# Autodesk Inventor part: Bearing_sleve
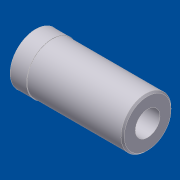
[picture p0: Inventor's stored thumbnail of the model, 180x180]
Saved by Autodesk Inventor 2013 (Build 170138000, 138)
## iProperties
Shininess: 50.0
Length Units: 11269
Angle Units: 11279
Time Units: 11290
Mass Units: 11283
Length Display Precision: 3
Angle Display Precision: 2
Created: 2001-04
Part Number: Bearing_sleve
Material: Standard
Document SubType Name: Modellieren
Designer: dl
Density: 1 g/cm^3
Density: 0.0
Volumn: 0.0
Area: 0.0
PropertySet Name: Model Information
Control State: 0
Master: False
Checked Out: False
Author: dl
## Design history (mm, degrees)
body "Solid1"
sketch "Sketch2"
  geometry: C1 r 10 at (0, 0) reference; 1 further point
  constraints: 1 coincident
revolve "Revolution1" stored, may be unused: angle "d6" = 90 deg
hole "Hole1" sketch "Sketch2" diameter "d7" = 15; stored, may be unused: countersink angle "d11" = 60 deg, drill point angle "d13" = 118 deg; dims "d8" = 6, "d9" = 4, "d10" = 2, "d12" = 8
chamfer "Chamfer1" distance "d14" = 1; stored, may be unused: second distance "d15" = 1, angle "d16" = 45 deg
sketch "Sketch1"
  geometry: L1 (0, 0)-(0, 10); L2 (0, 10)-(2, 10); L3 (2, 10)-(2, 15.5); L4 (2, 15.5)-(12, 15.5); L5 (12, 15.5)-(12, 15.2); L6 (12, 15.2)-(70, 15.2); L7 (70, 15.2)-(70, 0); L8 (70, 0)-(0, 0)
  constraints: 16 end point, 6 parallel, 1 perpendicular, 1 vertical
  dimensions: "d0" = 2 distance of L1.end L2.end; "d1" = 10 distance of L1.start L1.end; "d2" = 15.5 distance between parallel lines of L8 L4; "d3" = 10 distance of L3.end L4.end; "d4" = 15.2 distance of L6.end L7.end; "d5" = 70 distance of L7.end L1.start
